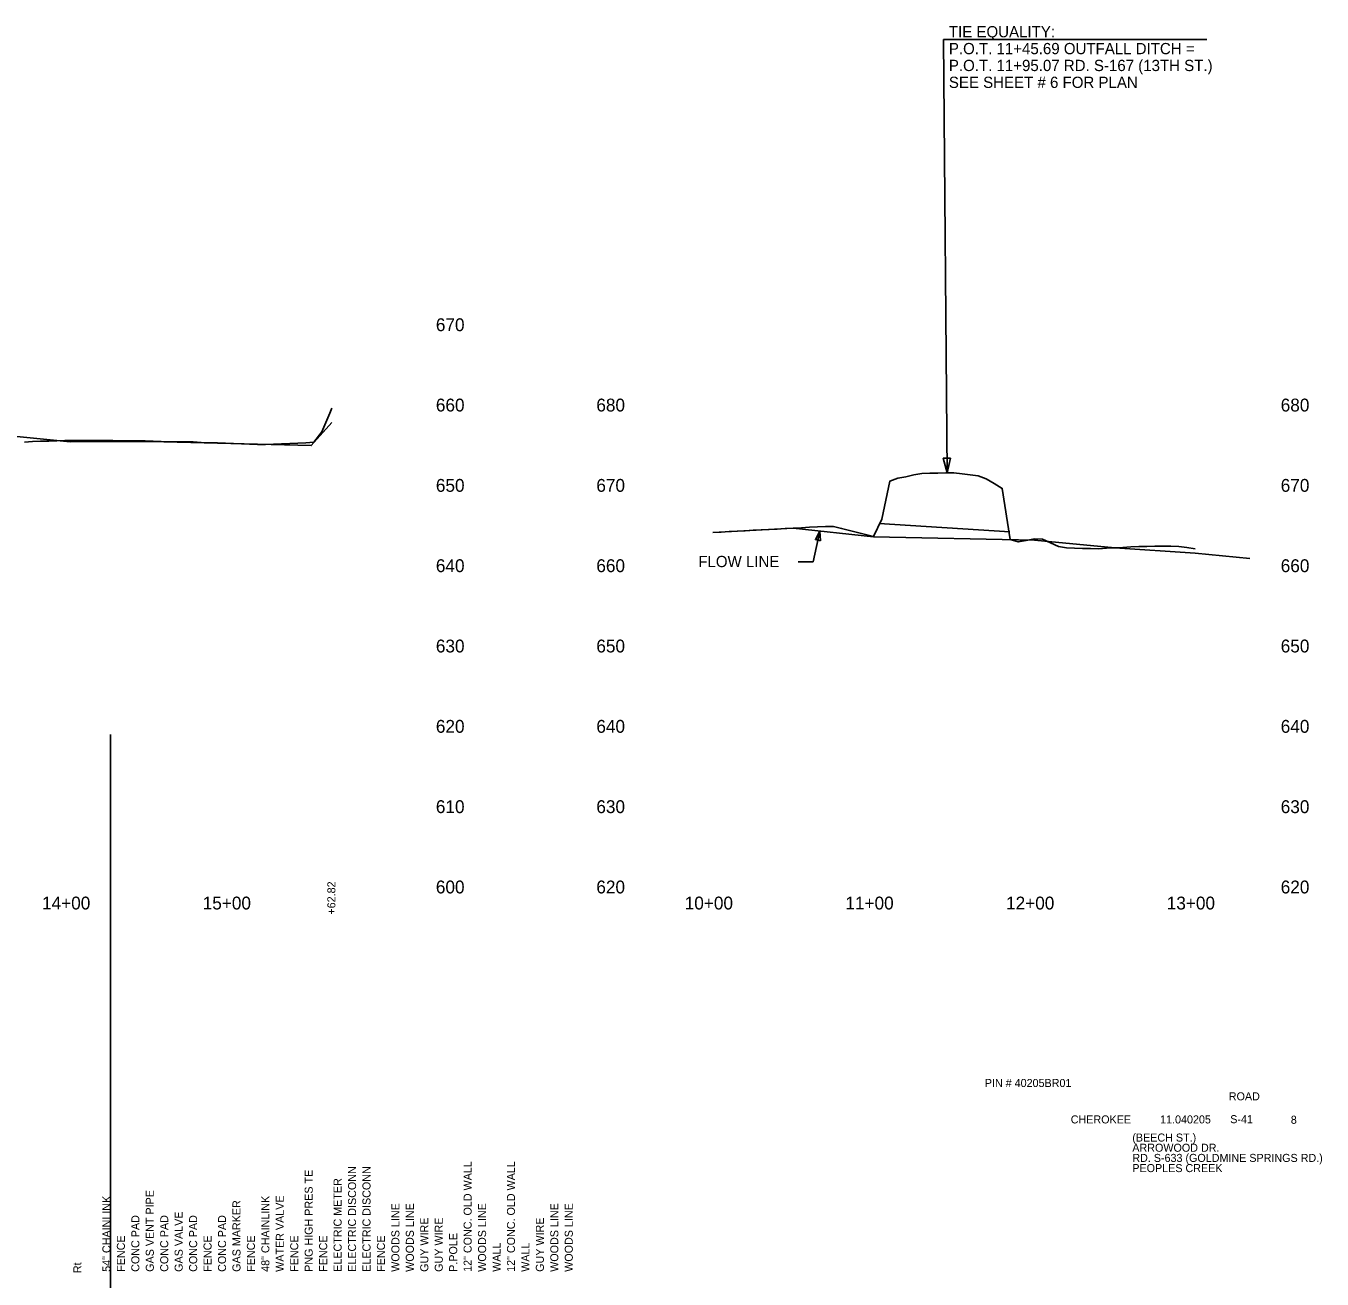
# Model space of a CAD drawing. Extents: x 16382402 to 16388022, y 46194326 to 46202918.
# Drawn here: x 16385124 to 16385930, y 46197682 to 46198462 of the extents above; entities that cross this region are included whole.
import ezdxf

# ---------------------------------------------------------------- set-up
doc = ezdxf.new("R2010")
doc.units = 0
for name, color, linetype in [('Default', 7, 'Continuous'), ('RD_DDB_ElevTX', 7, 'Continuous'), ('RD_DDB_Profile_EX', 7, 'Continuous'), ('RD_DDB_Profile_Lbl', 7, 'Continuous'), ('RD_DDB_StaTX', 7, 'Continuous'), ('RD_EX_H2O_WetLd', 7, 'Continuous'), ('RD_EX_Misc', 7, 'Continuous'), ('RD_GPK_Profile_Cell', 7, 'Continuous'), ('RD_HC_Data', 7, 'Continuous'), ('RD_TX_Bldg', 7, 'Continuous'), ('RD_TX_Drainage', 7, 'Continuous'), ('RD_TX_Misc1', 7, 'Continuous')]:
    doc.layers.add(name, color=color, linetype=linetype)

msp = doc.modelspace()

# ---------------------------------------------------------------- linework, layer by layer
at = {"layer": 'Default'}
msp.add_line((16385654.7, 46198152.02), (16385736.11, 46198146.83), dxfattribs=at)
at = {"layer": 'RD_DDB_Profile_EX'}
for points in [[(16385122.89, 46198202.66), (16385127.89, 46198203.04), (16385132.89, 46198203.22), (16385137.89, 46198203.31), (16385142.89, 46198203.56), (16385147.89, 46198203.8), (16385152.89, 46198203.78), (16385157.89, 46198203.76), (16385162.89, 46198203.77), (16385167.89, 46198203.83), (16385172.89, 46198203.78), (16385177.89, 46198203.7), (16385182.89, 46198203.58), (16385187.89, 46198203.52), (16385192.89, 46198203.48), (16385197.89, 46198203.44), (16385202.89, 46198203.28), (16385207.89, 46198203.07), (16385212.89, 46198202.87), (16385217.89, 46198202.85), (16385222.89, 46198202.85), (16385227.89, 46198202.84), (16385232.89, 46198202.54), (16385237.89, 46198202.37), (16385242.89, 46198202.2), (16385247.89, 46198202.03), (16385252.89, 46198201.86), (16385257.89, 46198201.65), (16385262.89, 46198201.5), (16385267.89, 46198201.34), (16385272.89, 46198201.2), (16385277.89, 46198201.37), (16385282.89, 46198201.6), (16385287.89, 46198201.84), (16385292.89, 46198202.11), (16385297.89, 46198202.37), (16385302.89, 46198202.64), (16385307.89, 46198209.2), (16385312.89, 46198220.81), (16385314.18, 46198223.8)], [(16385551.35, 46198146.5), (16385556.35, 46198146.77), (16385561.35, 46198147.03), (16385566.35, 46198147.3), (16385571.35, 46198147.57), (16385576.35, 46198147.83), (16385581.35, 46198148.1), (16385586.35, 46198148.37), (16385591.35, 46198148.63), (16385596.35, 46198148.9), (16385601.35, 46198149.17), (16385606.35, 46198149.43), (16385611.35, 46198149.7), (16385616.35, 46198149.97), (16385621.35, 46198150.23), (16385626.35, 46198150.21), (16385631.35, 46198148.97), (16385636.35, 46198147.72), (16385641.35, 46198146.48), (16385646.35, 46198145.24), (16385651.35, 46198144), (16385656.35, 46198154.78), (16385661.35, 46198178.42), (16385666.35, 46198180.35), (16385671.35, 46198181.11), (16385676.35, 46198182.29), (16385681.35, 46198183.14), (16385686.35, 46198183.32), (16385691.35, 46198183.5), (16385696.35, 46198183.68), (16385701.35, 46198183.65), (16385706.35, 46198183.02), (16385711.35, 46198182.4), (16385716.35, 46198181.78), (16385721.35, 46198179.82), (16385726.35, 46198176.88), (16385731.35, 46198173.9), (16385736.35, 46198142.18), (16385741.35, 46198140.64), (16385746.35, 46198141.54), (16385751.35, 46198142.44), (16385756.35, 46198142.32), (16385761.35, 46198140), (16385766.35, 46198137.69), (16385771.35, 46198136.93), (16385776.35, 46198136.76), (16385781.35, 46198136.59), (16385786.35, 46198136.42), (16385791.35, 46198136.37), (16385796.35, 46198136.65), (16385801.35, 46198136.93), (16385806.35, 46198137.21), (16385811.35, 46198137.49), (16385816.35, 46198137.77), (16385821.35, 46198137.85), (16385826.35, 46198137.91), (16385831.35, 46198137.96), (16385836.35, 46198138.02), (16385841.35, 46198137.73), (16385846.35, 46198137.06), (16385851.35, 46198136.38)]]:
    msp.add_lwpolyline(points, dxfattribs=at)
at = {"layer": 'RD_EX_H2O_WetLd'}
for points in [[(16384392.89, 46198229.62), (16384401.35, 46198229.94), (16384451.35, 46198231.49), (16384501.35, 46198228.96), (16384551.35, 46198227.05), (16384601.35, 46198226.33), (16384651.35, 46198226.63), (16384701.35, 46198223.9), (16384751.35, 46198222.99), (16384801.35, 46198221.94), (16384851.35, 46198211.07), (16384901.35, 46198211.92), (16384951.35, 46198214.72), (16385001.35, 46198212.13), (16385051.35, 46198205.81), (16385101.35, 46198207.82), (16385151.35, 46198203), (16385201.35, 46198203.03), (16385251.35, 46198201.92), (16385301.35, 46198200.55), (16385314.17, 46198214.95)], [(16385551.35, 46198146.5), (16385601.35, 46198149.17), (16385651.35, 46198143.71), (16385751.35, 46198141.78), (16385801.35, 46198136.84), (16385851.35, 46198133.53), (16385885.45, 46198130.18)]]:
    msp.add_lwpolyline(points, dxfattribs=at)
at = {"layer": 'RD_GPK_Profile_Cell'}
msp.add_line((16385176.35, 46196770.8), (16385176.35, 46198020.8), dxfattribs=at)
at = {"layer": 'RD_HC_Data'}
for q in [(16385858.68, 46198453.29), (16385697.04, 46198183.68)]:
    msp.add_line((16385694.73, 46198453.29), q, dxfattribs=at)
at = {"layer": 'RD_TX_Drainage'}
for points in [[(16385699.21, 46198192.7), (16385697.04, 46198183.68), (16385694.71, 46198192.66)], [(16385618.17, 46198141.37), (16385617.88, 46198147.36), (16385615.14, 46198142.03)]]:
    msp.add_lwpolyline(points, close=True, dxfattribs=at)
at = {"layer": 'RD_TX_Misc1'}
for p, q in [((16385613.76, 46198128.3), (16385617.88, 46198147.36)), ((16385604.41, 46198128.3), (16385613.76, 46198128.3))]:
    msp.add_line(p, q, dxfattribs=at)

# ---------------------------------------------------------------- texts
at = {"layer": 'RD_DDB_ElevTX'}
for s, p in [('670', (16385378.87, 46198271.8)), ('660', (16385378.87, 46198221.8)), ('680', (16385478.75, 46198221.8)), ('680', (16385904.69, 46198221.8)), ('650', (16385378.87, 46198171.8)), ('670', (16385478.75, 46198171.8)), ('670', (16385904.69, 46198171.8)), ('640', (16385378.87, 46198121.8)), ('660', (16385478.75, 46198121.8)), ('660', (16385904.69, 46198121.8)), ('630', (16385378.87, 46198071.8)), ('650', (16385478.75, 46198071.8)), ('650', (16385904.69, 46198071.8)), ('620', (16385378.87, 46198021.8)), ('640', (16385478.75, 46198021.8)), ('640', (16385904.69, 46198021.8)), ('610', (16385378.87, 46197971.8)), ('630', (16385478.75, 46197971.8)), ('630', (16385904.69, 46197971.8)), ('600', (16385378.87, 46197921.8)), ('620', (16385478.75, 46197921.8)), ('620', (16385904.69, 46197921.8))]:
    msp.add_text(s, height=8, dxfattribs=at).set_placement(p)
at = {"layer": 'RD_DDB_Profile_Lbl'}
msp.add_text('FLOW LINE', height=7, dxfattribs=at).set_placement((16385542.22, 46198124.91))
at = {"layer": 'RD_DDB_StaTX'}
msp.add_text('+62.82', height=5, rotation=90, dxfattribs=at).set_placement((16385316.34, 46197908.61))
for s, p in [('14+00', (16385133.76, 46197911.8)), ('14+00', (16385133.76, 46197911.8)), ('15+00', (16385233.76, 46197911.8)), ('15+00', (16385233.76, 46197911.8)), ('10+00', (16385533.76, 46197911.8)), ('11+00', (16385633.76, 46197911.8)), ('12+00', (16385733.76, 46197911.8)), ('13+00', (16385833.76, 46197911.8))]:
    msp.add_text(s, height=8, dxfattribs=at).set_placement(p)
at = {"layer": 'RD_EX_Misc'}
for s, p in [('PIN # 40205BR01', (16385720.53, 46197801.3)), ('ROAD', (16385872.38, 46197792.99)), ('CHEROKEE', (16385774.02, 46197778.61)), ('11.040205 ', (16385829.63, 46197778.61)), ('S-41', (16385873.26, 46197778.76)), ('8', (16385910.98, 46197778.4)), ('(BEECH ST.)', (16385812.34, 46197767.32)), ('ARROWOOD DR.', (16385812.34, 46197760.99)), ('RD. S-633 (GOLDMINE SPRINGS RD.)', (16385812.34, 46197754.65)), ('PEOPLES CREEK', (16385812.34, 46197748.31))]:
    msp.add_text(s, height=5, dxfattribs=at).set_placement(p)
at = {"layer": 'RD_HC_Data'}
for s, p in [('TIE EQUALITY:', (16385698.16, 46198454.71)), ('P.O.T. 11+45.69 OUTFALL DITCH =', (16385698.16, 46198444.21)), ('P.O.T. 11+95.07 RD. S-167 (13TH ST.)', (16385698.16, 46198433.71)), ('SEE SHEET # 6 FOR PLAN', (16385698.16, 46198423.21))]:
    msp.add_text(s, height=7, dxfattribs=at).set_placement(p)
at = {"layer": 'RD_TX_Bldg'}
for s, p in [('12" CONC. OLD WALL', (16385401.14, 46197686.23)), ('12" CONC. OLD WALL', (16385428.12, 46197686.23)), ('PNG HIGH PRES TE', (16385302.23, 46197686.23)), ('ELECTRIC DISCONN', (16385329.21, 46197686.23)), ('ELECTRIC DISCONN', (16385338.2, 46197686.23)), ('GAS VENT PIPE', (16385203.33, 46197686.23)), ('ELECTRIC METER', (16385320.22, 46197686.23)), ('54" CHAINLINK', (16385176.35, 46197686.23)), ('GAS MARKER', (16385257.28, 46197686.23)), ('48" CHAINLINK', (16385275.26, 46197686.23)), ('WATER VALVE', (16385284.25, 46197686.23)), ('CONC PAD', (16385194.33, 46197686.23)), ('CONC PAD', (16385212.32, 46197686.23)), ('GAS VALVE', (16385221.31, 46197686.23)), ('CONC PAD', (16385230.3, 46197686.23)), ('CONC PAD', (16385248.28, 46197686.23)), ('WOODS LINE', (16385356.19, 46197686.23)), ('WOODS LINE', (16385365.18, 46197686.23)), ('WOODS LINE', (16385410.14, 46197686.23)), ('WOODS LINE', (16385455.09, 46197686.23)), ('WOODS LINE', (16385464.09, 46197686.23)), ('GUY WIRE', (16385374.17, 46197686.23)), ('GUY WIRE', (16385383.16, 46197686.23)), ('GUY WIRE', (16385446.1, 46197686.23)), ('FENCE', (16385185.34, 46197686.23)), ('FENCE', (16385239.29, 46197686.23)), ('FENCE', (16385266.27, 46197686.23)), ('FENCE', (16385293.24, 46197686.23)), ('FENCE', (16385311.23, 46197686.23)), ('FENCE', (16385347.19, 46197686.23)), ('P.POLE', (16385392.15, 46197686.23)), ('WALL', (16385419.13, 46197686.23)), ('WALL', (16385437.11, 46197686.23)), ('Rt', (16385158.24, 46197685.43))]:
    msp.add_text(s, height=5, rotation=90, dxfattribs=at).set_placement(p)

doc.saveas('drawing.dxf')
